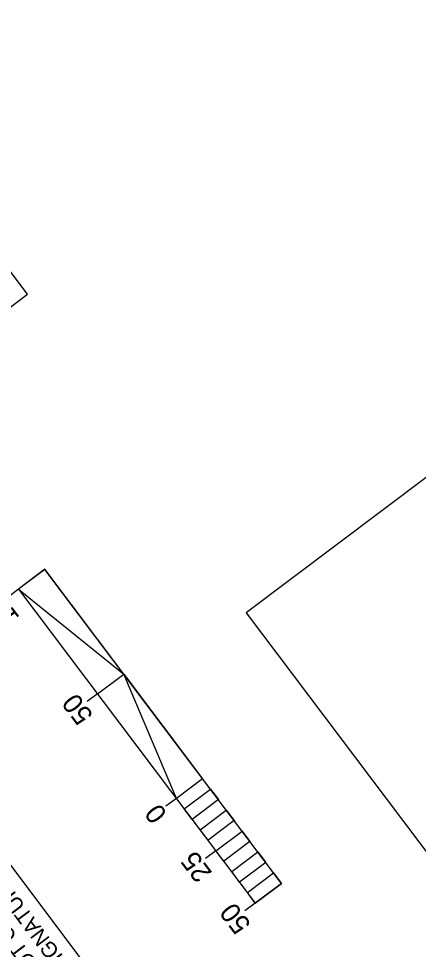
# Model space of a CAD drawing. Extents: x 1263113 to 1265001, y 775064 to 777068.
# Drawn here: x 1263346 to 1263498.2, y 776151.3 to 776506.1 of the extents above; entities that cross this region are included whole.
import ezdxf

# ---------------------------------------------------------------- set-up
doc = ezdxf.new("R2010")
doc.units = 0
for name, color, linetype in [('Sheet Data Field CELL', 7, 'Continuous'), ('Sheet Sticker Exception Certification CELL', 7, 'Continuous'), ('Sheet Title CELL', 7, 'Continuous'), ('Sheet Typical CELL', 7, 'Continuous')]:
    doc.layers.add(name, color=color, linetype=linetype)

msp = doc.modelspace()

# ---------------------------------------------------------------- linework, layer by layer
at = {"layer": 'Sheet Data Field CELL'}
for p, q in [((1263376, 776248.75), (1263372.02, 776245.75)), ((1263421.06, 776188.94), (1263417.07, 776185.94)), ((1263436.07, 776169), (1263432.09, 776166))]:
    msp.add_line(p, q, dxfattribs=at)
msp.add_lwpolyline([(1263349.4, 776401.09), (1263270.32, 776506.07), (1263251.38, 776491.8), (1263330.45, 776386.82)], close=True, dxfattribs=at)
at = {"layer": 'Sheet Sticker Exception Certification CELL'}
msp.add_line((1263281.87, 776264.34), (1263410.06, 776094.15), dxfattribs=at)
at = {"layer": 'Sheet Title CELL'}
for p, q in [((1263355.96, 776296.14), (1263345.98, 776288.62)), ((1263446.05, 776176.5), (1263355.96, 776296.14)), ((1263345.98, 776288.62), (1263341.99, 776285.62)), ((1263345.98, 776288.62), (1263436.08, 776168.99)), ((1263376.01, 776248.75), (1263385.98, 776256.25)), ((1263376.01, 776248.75), (1263372.04, 776245.75)), ((1263406.06, 776208.88), (1263402.07, 776205.87)), ((1263415.06, 776196.91), (1263425.03, 776204.42)), ((1263421.08, 776188.94), (1263417.08, 776185.93)), ((1263436.08, 776168.99), (1263446.05, 776176.5)), ((1263436.08, 776168.99), (1263432.11, 776166)), ((1263436.08, 776168.99), (1263436.08, 776168.99)), ((1263432.11, 776166), (1263432.11, 776166))]:
    msp.add_line(p, q, dxfattribs=at)
for points in [[(1263345.98, 776288.62), (1263385.98, 776256.25), (1263355.91, 776296.2)], [(1263406.06, 776208.88), (1263385.98, 776256.25), (1263416.03, 776216.39)], [(1263412.05, 776200.89), (1263409.05, 776204.88), (1263419.03, 776212.4), (1263422.02, 776208.4)], [(1263418.07, 776192.93), (1263415.06, 776196.91), (1263425.03, 776204.42), (1263428.03, 776200.43)], [(1263424.08, 776184.95), (1263421.08, 776188.94), (1263431.03, 776196.44), (1263434.04, 776192.45)], [(1263430.08, 776176.97), (1263427.08, 776180.96), (1263437.05, 776188.47), (1263440.05, 776184.49)], [(1263436.08, 776168.99), (1263433.08, 776172.98), (1263443.05, 776180.49), (1263446.05, 776176.5)]]:
    msp.add_lwpolyline(points, close=True, dxfattribs=at)
at = {"layer": 'Sheet Typical CELL'}
msp.add_lwpolyline([(1263432.63, 776279.56), (1264082.63, 775416.59), (1264341.8, 775611.8), (1263691.81, 776474.77)], close=True, dxfattribs=at)

# ---------------------------------------------------------------- texts
at = {"layer": 'Sheet Data Field CELL'}
for s, p in [('100', (1263346.6, 776277.82)), ('50', (1263374.65, 776240.6)), ('25', (1263419.9, 776180.52)), ('50', (1263434.72, 776160.85))]:
    msp.add_text(s, height=7.488, rotation=126.9874, dxfattribs=at).set_placement(p)
at = {"layer": 'Sheet Sticker Exception Certification CELL'}
for s, p in [('UNLESS ALL SIGNATURES COMPLETED', (1263396.1, 776104.98)), ('DOCUMENT NOT CONSIDERED FINAL', (1263385.36, 776103.65))]:
    msp.add_text(s, height=5.8579, rotation=126.9874, dxfattribs=at).set_placement(p)
at = {"layer": 'Sheet Title CELL'}
msp.add_text('0', height=7.49, rotation=126.9874, dxfattribs=at).set_placement((1263402.81, 776202.99))

doc.saveas('drawing.dxf')
